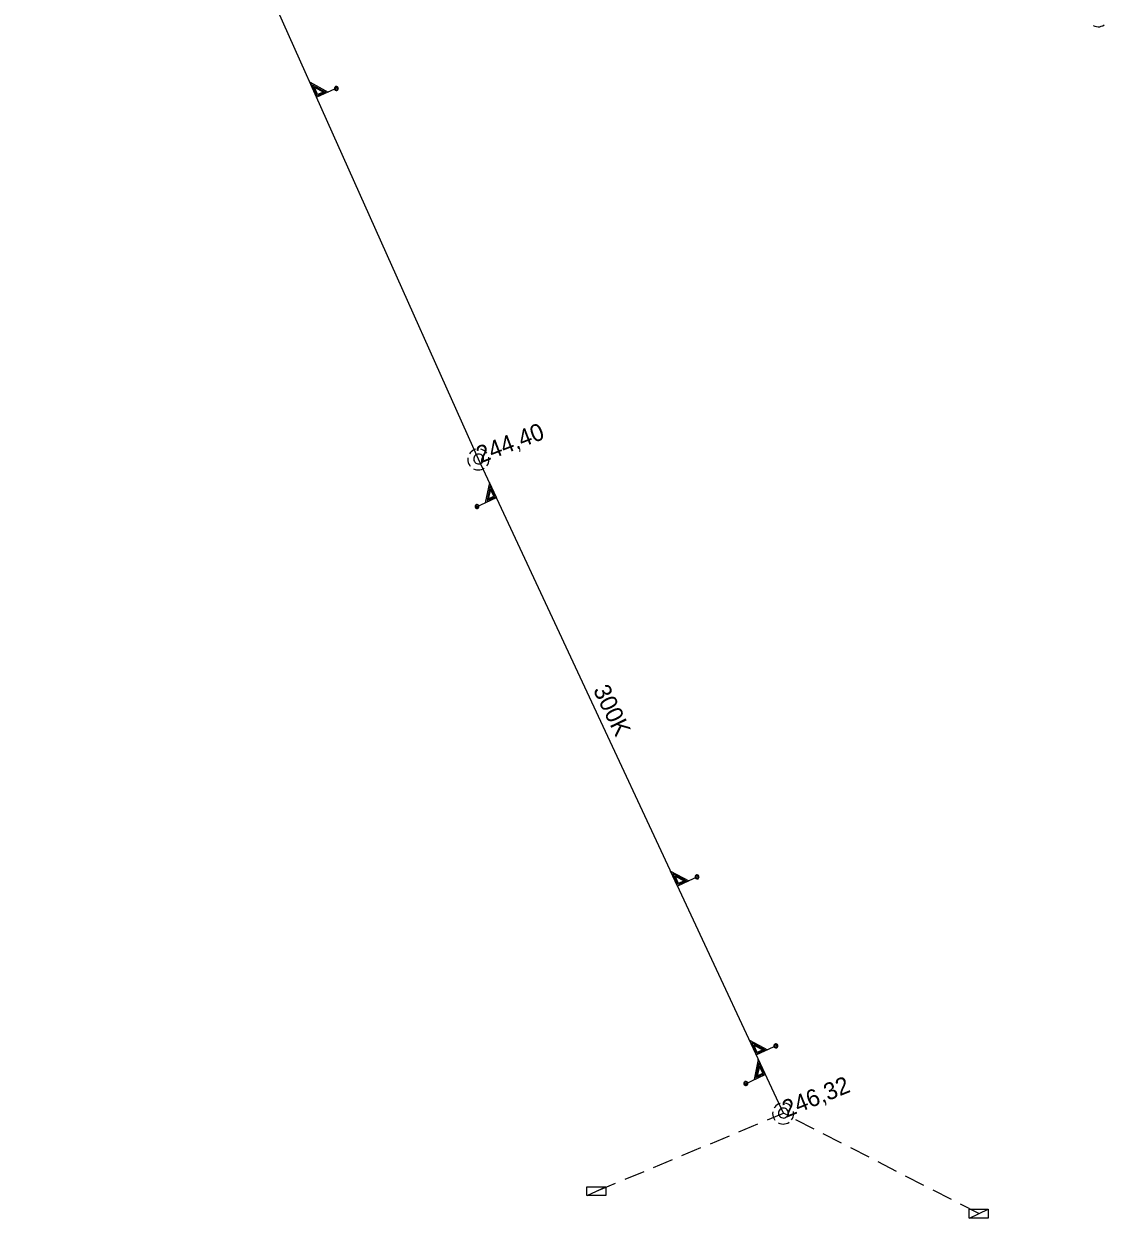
# Model space of a CAD drawing. Extents: x -735085 to -733500, y -1044153 to -1043402.
# Drawn here: x -734807.1 to -734756.7, y -1043713.7 to -1043658 of the extents above; entities that cross this region are included whole.
import ezdxf

# ---------------------------------------------------------------- set-up
doc = ezdxf.new("R2010")
doc.units = 0
doc.header["$LTSCALE"] = 0.32
doc.linetypes.add('MEDIUM_DASHED', pattern=[4.5, 3, -1.5])
doc.layers.add('16', color=7, linetype='Continuous')
for name, color, linetype, lineweight in [('18', 7, 'Continuous', 13), ('20', 7, 'Continuous', 13), ('49', 7, 'Continuous', 13)]:
    doc.layers.add(name, color=color, linetype=linetype, lineweight=lineweight)

msp = doc.modelspace()

# ---------------------------------------------------------------- linework, layer by layer
at = {"layer": '18'}
for p, q in [((-734780.862, -1043712.64), (-734779.988, -1043712.228)), ((-734763.021, -1043713.69), (-734762.147, -1043713.278))]:
    msp.add_line(p, q, dxfattribs=at)
for points in [[(-734757.24, -1043658.046), (-734757.17, -1043658.077), (-734757.095, -1043658.096), (-734757.019, -1043658.103), (-734756.942, -1043658.098), (-734756.867, -1043658.081), (-734756.795, -1043658.053), (-734756.735, -1043658.018)], [(-734792.47, -1043660.943), (-734793.47, -1043661.391), (-734793.784, -1043660.688), (-734792.942, -1043661.155)], [(-734793.071, -1043661.157), (-734793.45, -1043661.327), (-734793.681, -1043660.81), (-734793.07, -1043661.157)], [(-734793.166, -1043661.148), (-734793.433, -1043661.268), (-734793.585, -1043660.928), (-734793.166, -1043661.149)], [(-734786.073, -1043677.817), (-734786.144, -1043677.845), (-734786.211, -1043677.884), (-734786.271, -1043677.932), (-734786.322, -1043677.989), (-734786.346, -1043678.023)], [(-734785.532, -1043678), (-734785.582, -1043677.942), (-734785.64, -1043677.892), (-734785.705, -1043677.851), (-734785.776, -1043677.822), (-734785.825, -1043677.808)], [(-734786.418, -1043678.209), (-734786.424, -1043678.286), (-734786.419, -1043678.363), (-734786.402, -1043678.438), (-734786.373, -1043678.509), (-734786.333, -1043678.575), (-734786.317, -1043678.597)], [(-734785.537, -1043678.586), (-734785.496, -1043678.521), (-734785.465, -1043678.451), (-734785.446, -1043678.376), (-734785.438, -1043678.3), (-734785.443, -1043678.223), (-734785.449, -1043678.188)], [(-734786.16, -1043678.726), (-734786.09, -1043678.757), (-734786.015, -1043678.776), (-734785.939, -1043678.783), (-734785.862, -1043678.778), (-734785.787, -1043678.761), (-734785.715, -1043678.733), (-734785.655, -1043678.698)], [(-734786.081, -1043680.527), (-734785.088, -1043680.064), (-734785.414, -1043679.365), (-734785.612, -1043680.308)], [(-734785.526, -1043680.212), (-734785.149, -1043680.036), (-734785.388, -1043679.523), (-734785.528, -1043680.213)], [(-734785.47, -1043680.134), (-734785.206, -1043680.011), (-734785.362, -1043679.675), (-734785.47, -1043680.135)], [(-734775.643, -1043697.731), (-734776.636, -1043698.194), (-734776.961, -1043697.496), (-734776.112, -1043697.949)], [(-734776.24, -1043697.954), (-734776.617, -1043698.13), (-734776.856, -1043697.617), (-734776.239, -1043697.953)], [(-734776.336, -1043697.947), (-734776.601, -1043698.07), (-734776.758, -1043697.733), (-734776.336, -1043697.948)], [(-734771.968, -1043705.616), (-734772.961, -1043706.079), (-734773.286, -1043705.381), (-734772.437, -1043705.834)], [(-734772.565, -1043705.839), (-734772.942, -1043706.015), (-734773.181, -1043705.502), (-734772.564, -1043705.838)], [(-734772.661, -1043705.832), (-734772.926, -1043705.955), (-734773.083, -1043705.618), (-734772.661, -1043705.833)], [(-734773.538, -1043707.448), (-734772.545, -1043706.985), (-734772.871, -1043706.286), (-734773.069, -1043707.229)], [(-734772.983, -1043707.133), (-734772.606, -1043706.957), (-734772.845, -1043706.444), (-734772.985, -1043707.134)], [(-734772.927, -1043707.055), (-734772.663, -1043706.932), (-734772.819, -1043706.596), (-734772.927, -1043707.056)], [(-734771.852, -1043708.337), (-734771.923, -1043708.365), (-734771.99, -1043708.404), (-734772.05, -1043708.452), (-734772.101, -1043708.509), (-734772.125, -1043708.543)], [(-734771.311, -1043708.52), (-734771.361, -1043708.462), (-734771.419, -1043708.412), (-734771.484, -1043708.371), (-734771.555, -1043708.342), (-734771.604, -1043708.328)], [(-734772.197, -1043708.729), (-734772.203, -1043708.806), (-734772.198, -1043708.883), (-734772.181, -1043708.958), (-734772.152, -1043709.029), (-734772.112, -1043709.095), (-734772.096, -1043709.117)], [(-734771.316, -1043709.106), (-734771.275, -1043709.041), (-734771.244, -1043708.971), (-734771.225, -1043708.896), (-734771.217, -1043708.82), (-734771.222, -1043708.743), (-734771.228, -1043708.708)], [(-734771.939, -1043709.246), (-734771.869, -1043709.277), (-734771.794, -1043709.296), (-734771.718, -1043709.303), (-734771.641, -1043709.298), (-734771.566, -1043709.281), (-734771.494, -1043709.253), (-734771.434, -1043709.218)]]:
    msp.add_lwpolyline(points, dxfattribs=at)
for points in [[(-734792.595, -1043660.896), (-734792.622, -1043660.915), (-734792.642, -1043660.942), (-734792.65, -1043660.975), (-734792.646, -1043661.008), (-734792.632, -1043661.038), (-734792.608, -1043661.061), (-734792.576, -1043661.074), (-734792.543, -1043661.075), (-734792.511, -1043661.065), (-734792.486, -1043661.044), (-734792.468, -1043661.016), (-734792.462, -1043660.982), (-734792.468, -1043660.95), (-734792.484, -1043660.92), (-734792.51, -1043660.899), (-734792.542, -1043660.889), (-734792.576, -1043660.89)], [(-734792.585, -1043660.921), (-734792.608, -1043660.938), (-734792.622, -1043660.962), (-734792.624, -1043660.99), (-734792.615, -1043661.017), (-734792.596, -1043661.038), (-734792.569, -1043661.048), (-734792.541, -1043661.047), (-734792.516, -1043661.035), (-734792.498, -1043661.014), (-734792.491, -1043660.986), (-734792.494, -1043660.958), (-734792.509, -1043660.935), (-734792.534, -1043660.919), (-734792.561, -1043660.915)], [(-734785.689, -1043678.269), (-734785.695, -1043678.217), (-734785.713, -1043678.167), (-734785.741, -1043678.123), (-734785.779, -1043678.086), (-734785.824, -1043678.059), (-734785.874, -1043678.043), (-734785.926, -1043678.038), (-734785.978, -1043678.045), (-734786.027, -1043678.064), (-734786.071, -1043678.094), (-734786.106, -1043678.133), (-734786.132, -1043678.178), (-734786.147, -1043678.229), (-734786.15, -1043678.281), (-734786.142, -1043678.333), (-734786.121, -1043678.381), (-734786.091, -1043678.424), (-734786.051, -1043678.459), (-734786.005, -1043678.483), (-734785.954, -1043678.497), (-734785.902, -1043678.499), (-734785.85, -1043678.489), (-734785.802, -1043678.467), (-734785.76, -1043678.435), (-734785.727, -1043678.395), (-734785.703, -1043678.348), (-734785.691, -1043678.297)], [(-734786.036, -1043680.401), (-734786.063, -1043680.42), (-734786.082, -1043680.448), (-734786.09, -1043680.48), (-734786.086, -1043680.514), (-734786.071, -1043680.543), (-734786.046, -1043680.566), (-734786.015, -1043680.579), (-734785.981, -1043680.58), (-734785.95, -1043680.569), (-734785.923, -1043680.547), (-734785.907, -1043680.519), (-734785.901, -1043680.486), (-734785.908, -1043680.453), (-734785.925, -1043680.424), (-734785.951, -1043680.403), (-734785.983, -1043680.393), (-734786.017, -1043680.394)], [(-734786.023, -1043680.425), (-734786.045, -1043680.442), (-734786.059, -1043680.467), (-734786.062, -1043680.495), (-734786.051, -1043680.522), (-734786.032, -1043680.541), (-734786.006, -1043680.552), (-734785.978, -1043680.551), (-734785.952, -1043680.538), (-734785.935, -1043680.516), (-734785.927, -1043680.489), (-734785.932, -1043680.461), (-734785.947, -1043680.438), (-734785.971, -1043680.423), (-734786, -1043680.418)], [(-734775.768, -1043697.686), (-734775.796, -1043697.705), (-734775.815, -1043697.733), (-734775.823, -1043697.765), (-734775.818, -1043697.798), (-734775.804, -1043697.828), (-734775.779, -1043697.85), (-734775.747, -1043697.863), (-734775.714, -1043697.864), (-734775.683, -1043697.853), (-734775.657, -1043697.832), (-734775.64, -1043697.803), (-734775.634, -1043697.77), (-734775.64, -1043697.737), (-734775.658, -1043697.708), (-734775.684, -1043697.687), (-734775.716, -1043697.678), (-734775.749, -1043697.679)], [(-734775.758, -1043697.71), (-734775.781, -1043697.728), (-734775.795, -1043697.752), (-734775.796, -1043697.78), (-734775.787, -1043697.807), (-734775.767, -1043697.827), (-734775.741, -1043697.837), (-734775.713, -1043697.836), (-734775.688, -1043697.823), (-734775.67, -1043697.802), (-734775.663, -1043697.774), (-734775.667, -1043697.747), (-734775.683, -1043697.723), (-734775.707, -1043697.708), (-734775.734, -1043697.704)], [(-734772.093, -1043705.571), (-734772.121, -1043705.59), (-734772.14, -1043705.618), (-734772.148, -1043705.65), (-734772.143, -1043705.683), (-734772.129, -1043705.713), (-734772.104, -1043705.735), (-734772.072, -1043705.748), (-734772.039, -1043705.749), (-734772.008, -1043705.738), (-734771.982, -1043705.717), (-734771.965, -1043705.688), (-734771.959, -1043705.655), (-734771.965, -1043705.622), (-734771.983, -1043705.593), (-734772.009, -1043705.572), (-734772.041, -1043705.563), (-734772.074, -1043705.564)], [(-734772.083, -1043705.595), (-734772.106, -1043705.613), (-734772.12, -1043705.637), (-734772.121, -1043705.665), (-734772.112, -1043705.692), (-734772.092, -1043705.712), (-734772.066, -1043705.722), (-734772.038, -1043705.721), (-734772.013, -1043705.708), (-734771.995, -1043705.687), (-734771.988, -1043705.659), (-734771.992, -1043705.632), (-734772.008, -1043705.608), (-734772.032, -1043705.593), (-734772.059, -1043705.589)], [(-734773.493, -1043707.322), (-734773.52, -1043707.341), (-734773.539, -1043707.369), (-734773.547, -1043707.401), (-734773.543, -1043707.435), (-734773.528, -1043707.464), (-734773.503, -1043707.487), (-734773.472, -1043707.5), (-734773.438, -1043707.501), (-734773.407, -1043707.49), (-734773.38, -1043707.468), (-734773.364, -1043707.44), (-734773.358, -1043707.407), (-734773.365, -1043707.374), (-734773.382, -1043707.345), (-734773.408, -1043707.324), (-734773.44, -1043707.314), (-734773.474, -1043707.315)], [(-734773.48, -1043707.346), (-734773.502, -1043707.363), (-734773.516, -1043707.388), (-734773.519, -1043707.416), (-734773.508, -1043707.443), (-734773.489, -1043707.462), (-734773.463, -1043707.473), (-734773.435, -1043707.472), (-734773.409, -1043707.459), (-734773.392, -1043707.437), (-734773.384, -1043707.41), (-734773.389, -1043707.382), (-734773.404, -1043707.359), (-734773.428, -1043707.344), (-734773.457, -1043707.339)], [(-734771.468, -1043708.789), (-734771.474, -1043708.737), (-734771.492, -1043708.687), (-734771.52, -1043708.643), (-734771.558, -1043708.606), (-734771.603, -1043708.579), (-734771.653, -1043708.563), (-734771.705, -1043708.558), (-734771.757, -1043708.565), (-734771.806, -1043708.584), (-734771.85, -1043708.614), (-734771.885, -1043708.653), (-734771.911, -1043708.698), (-734771.926, -1043708.749), (-734771.929, -1043708.801), (-734771.921, -1043708.853), (-734771.9, -1043708.901), (-734771.87, -1043708.944), (-734771.83, -1043708.979), (-734771.784, -1043709.003), (-734771.733, -1043709.017), (-734771.681, -1043709.019), (-734771.629, -1043709.009), (-734771.581, -1043708.987), (-734771.539, -1043708.955), (-734771.506, -1043708.915), (-734771.482, -1043708.868), (-734771.47, -1043708.817)], [(-734780.866, -1043712.228), (-734779.992, -1043712.228), (-734779.992, -1043712.64), (-734780.866, -1043712.64)], [(-734763.025, -1043713.278), (-734762.151, -1043713.278), (-734762.151, -1043713.69), (-734763.025, -1043713.69)]]:
    msp.add_lwpolyline(points, close=True, dxfattribs=at)
at = {"layer": '20'}
msp.add_lwpolyline([(-734771.699, -1043708.8), (-734785.92, -1043678.28), (-734807.14, -1043630.85)], dxfattribs=at)
msp.add_lwpolyline([(-734771.699, -1043708.8), (-734785.92, -1043678.28), (-734807.14, -1043630.85)], dxfattribs=at)
at = {"layer": '49', "linetype": 'MEDIUM_DASHED'}
for p in [(-734780.42, -1043712.43), (-734780.42, -1043712.43), (-734762.579, -1043713.48), (-734762.579, -1043713.48)]:
    msp.add_line(p, (-734771.699, -1043708.8), dxfattribs=at)

# ---------------------------------------------------------------- texts
at = {"layer": '16'}
for s, rotation, p in [('244,40', 21, (-734785.841, -1043678.48)), ('300K', 296, (-734780.599, -1043689.041)), ('246,32', 22, (-734771.556, -1043709.008))]:
    msp.add_text(s, height=0.8, rotation=rotation, dxfattribs=at).set_placement(p)

doc.saveas('drawing.dxf')
